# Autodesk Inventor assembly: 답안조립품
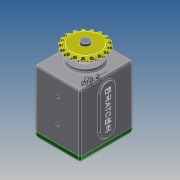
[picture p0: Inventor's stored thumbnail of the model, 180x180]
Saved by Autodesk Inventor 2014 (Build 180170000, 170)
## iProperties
Created: 2018-12
Part Number: 답안조립품
Document SubType Name: Assembly
Designer: kb542-15
Mass: 1863 g
Surface Area: 1968.34 cm^2
Volume: 815.225 cm^3
Density: 2.28526 g/cm^3
Author: kb542-15
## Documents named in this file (16)
- C:\Users\kb542-15\Desktop\381207V1015\답안조립품.iam
- C:\Users\kb542-15\Desktop\381207V1015\본체.ipt
- C:\Users\kb542-15\Desktop\381207V1015\커버.ipt
- C:\Users\kb542-15\Desktop\381207V1015\메인 기어 축.ipt
- C:\Users\kb542-15\Desktop\381207V1015\서브 기어 축.ipt
- C:\Users\kb542-15\Desktop\381207V1015\베어링 608.ipt
- C:\Users\kb542-15\Desktop\381207V1015\베어링 6003.ipt
- C:\Users\kb542-15\Desktop\381207V1015\오일 실 8 22 7.ipt
- C:\Users\kb542-15\Desktop\381207V1015\오일 실 17 32 8.ipt
- C:\Users\kb542-15\Desktop\381207V1015\키 5 x 5 x 18.ipt
- C:\Users\kb542-15\Desktop\381207V1015\스프로킷.ipt
- C:\Users\kb542-15\Desktop\381207V1015\멈춤나사 M3x8.ipt
- C:\Users\kb542-15\Desktop\381207V1015\부시.ipt
- C:\Users\kb542-15\Desktop\381207V1015\슬라이더.ipt
- C:\Users\kb542-15\Desktop\381207V1015\가변스프링.ipt
- C:\Users\kb542-15\Desktop\381207V1015\볼트 M4 x 10.ipt
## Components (1 placed, 1 different names)
1. 가변스프링:1
